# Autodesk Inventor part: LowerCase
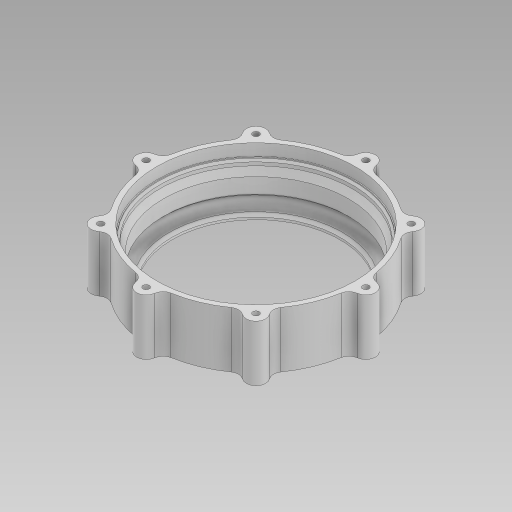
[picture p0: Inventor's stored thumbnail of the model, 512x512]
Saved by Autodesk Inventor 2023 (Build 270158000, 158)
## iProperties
Created: 2024-05
Part Number: LowerCase
Material: 一般
Document SubType Name: Modeling
Designer: kumagai
Density: 1 g/cm^3
Appearance: 既定
Author: kumagai
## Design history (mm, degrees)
derived "CoreSketch.ipt"
  sketch "Vertical"
    geometry: L1 (0, 65.337)-(0, -65.337) reference; L2 (-46.2, 0)-(46.2, 0) reference; L3 (-11, 2)-(11, 2) reference; L4 (11, 2)-(11, -2) reference; L5 (11, -2)-(-11, -2) reference; L6 (-11, -2)-(-11, 2) reference; L7 (11, 2)-(33, 2) reference; L8 (33, 2)-(33, -2) reference; L9 (33, -2)-(11, -2) reference; L10 (11, -2)-(11, 2) reference; L11 (22, 2.772)-(22, -2.683) reference; L12 (-33, 2)-(-11, 2) reference; L13 (-11, 2)-(-11, -2) reference; L14 (-11, -2)-(-33, -2) reference; L15 (-33, -2)-(-33, 2) reference; L16 (-22, 4.087)-(-22, -4.199) reference; L17 (-33, 10)-(-11, 10) reference; L18 (-11, 10)-(-11, 6) reference; L19 (-11, 6)-(-33, 6) reference; L20 (-33, 6)-(-33, 10) reference; L21 (-27.353, 10)-(-16.647, 10) reference; L22 (-16.647, 10)-(-16.647, 16) reference; L23 (-16.647, 16)-(-27.353, 16) reference; L24 (-27.353, 16)-(-27.353, 10) reference; L25 (11, 16)-(33, 16) reference; L26 (33, 16)-(33, 12) reference; L27 (33, 12)-(11, 12) reference; L28 (11, 12)-(11, 16) reference; L29 (16.134, 12)-(27.866, 12) reference; L30 (27.866, 12)-(27.866, 6) reference; L31 (27.866, 6)-(16.134, 6) reference; L32 (16.134, 6)-(16.134, 12) reference; L33 (-22, 18.272)-(-22, 9.031) reference; L34 (22, 22.635)-(22, 12.71) reference; L35 (33, -2)-(35, -2) reference; L36 (35, -2)-(35, 10) reference; L37 (35, 10)-(33, 10) reference; L38 (33, 10)-(33, -2) reference; L39 (0, -4)-(37.5, -4) reference; L40 (40.5, -1)-(40.5, 14) reference; L41 (43.9, -8)-(0, -8) reference; L42 (0, -4)-(0, -8) reference; L43 (35, -2)-(39, -2) reference; L44 (39, -2)-(39, 3.066) reference; L45 (38.45, 8.685)-(41.471, 10.429) reference; L46 (38.45, 10)-(35, 10) reference; L47 (40.5, 9.627)-(41.993, 8.375) reference; L48 (41.55, 3.315)-(40.5, 2.709) reference; L49 (37.5, -4)-(40.5, -1) reference; L50 (-43, 43.294)-(-1, 43.294) reference; L51 (-1, 43.294)-(-1, 26) reference; L52 (-1, 26)-(-43, 26) reference; L53 (-43, 26)-(-43, 43.294) reference; L54 (1, 43.294)-(43, 43.294) reference; L55 (43, 43.294)-(43, 26) reference; L56 (43, 26)-(1, 26) reference; L57 (1, 26)-(1, 43.294) reference; L58 (-22, 45.556)-(-22, 31.232) reference; L59 (22, 47.214)-(22, 32.287) reference; L60 (48, 5.268)-(48, -2.616) reference; L61 (43.6, -11)-(54, -11) reference; L62 (54, -11)-(54, 18) reference; L63 (45.222, -3.461)-(46.5, -2.566) reference; L64 (48, -2.616)-(49.192, -3.808) reference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; A1 r 3.1 centre (40, 6) between (39, 3.066) and (38.45, 8.685) reference; A2 r 3.1 centre (47, -6) between (45.222, -3.461) and (49.192, -3.808) reference; A3 r 3.1 centre (47, 13) between (43.9, 13) and (49, 10.631) reference; 2 further points; 1 other entity
    constraints: 1 other
  sketch "OuterLayout"
    geometry: L1 (0, -46.2)-(0, 46.2) reference; L2 (-73.4, 0)-(62.4, 0) reference; L3 (43, -21)-(1, -21) reference; L4 (1, -21)-(1, 21) reference; L5 (1, 21)-(43, 21) reference; L6 (43, 21)-(43, -21) reference; L7 (-1, -21)-(-43, -21) reference; L8 (-43, -21)-(-43, 21) reference; L9 (-43, 21)-(-1, 21) reference; L10 (-1, 21)-(-1, -21) reference; C1 r 11.1 at (22, 0) reference; C2 r 11.1 at (-22, 0) reference; C3 r 2.5 at (-22, 0) reference; C4 r 2.5 at (22, 0) reference; C5 r 1.6 at (-6.5, -15.5) reference; C6 r 1.6 at (-37.5, -15.5) reference; C7 r 1.6 at (-6.5, 15.5) reference; C8 r 1.6 at (-37.5, 15.5) reference; C9 r 51.5 at (0, 0) reference; C10 r 1.65 at (-57, 0) reference; A1 r 54 centre (0, 0) between (-53.229, -9.091) and (-53.229, 9.091) reference; A2 r 5 centre (-58.158, -9.933) between (-53.229, -9.091) and (-57.579, -4.966) reference; A3 r 5 centre (-58.158, 9.933) between (-57.579, 4.966) and (-53.229, 9.091) reference; A4 r 5 centre (-57, 0) between (-53.86, 3.891) and (-53.86, -3.891) reference; 1 further point
revolve "回転1" stored, may be unused: angle "d1" = 360 deg
sketch "スケッチ3"
  geometry: C1 r 1.65 at (-57, 0) reference; C2 r 2.65 at (-57, 0); A1 r 5 centre (-57, 0) between (-53.86, 3.891) and (-53.86, -3.891) reference; A2 r 5 centre (-58.158, 9.933) between (-57.579, 4.966) and (-53.229, 9.091) reference; A3 r 5 centre (-58.158, -9.933) between (-53.229, -9.091) and (-57.579, -4.966) reference; A4 r 54 centre (0, 0) between (-53.86, 3.891) and (-53.86, -3.891) reference; 1 further point
  constraints: 1 centre point, 1 coincident
  dimensions: "d2" = 5.3 diameter of C2
extrude "押し出し1" join sketch "スケッチ3" stored distance "d3" = 10; taper "d4" = 0 deg
extrude "押し出し2" cut sketch "スケッチ3" stored distance "d5" = 13; taper "d6" = 0 deg
chamfer "面取り1" distance "d7" = 1; stored, may be unused: second distance "d8" = 2, angle "d9" = 45 deg
pattern_circular "円形状パターン1" dims angle "d11" = 360 deg
node "ソリッド1"
